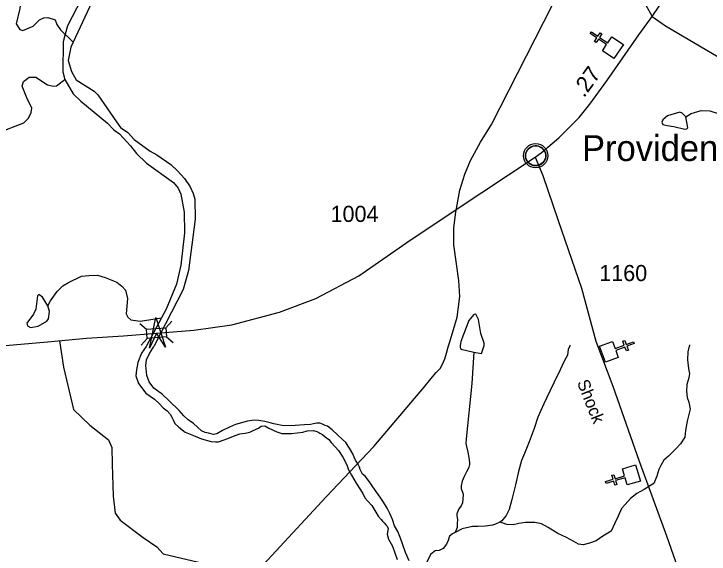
# Model space of a CAD drawing. Extents: x 2056842 to 2160602, y 826753 to 1016856.
# Drawn here: x 2095813 to 2101200, y 908514 to 912699 of the extents above; entities that cross this region are included whole.
import ezdxf

# ---------------------------------------------------------------- set-up
doc = ezdxf.new("R2010")
doc.units = 0
for name, color, linetype in [('Exist Civil Demographics Community CELL', 7, 'Continuous'), ('Exist Civil Demographics Community Label', 7, 'Continuous'), ('Exist Cultural Church CELL', 7, 'Continuous'), ('Exist Hydrographic Creek Single Shore', 7, 'Continuous'), ('Exist Hydrographic Misc Water Feature', 7, 'Continuous'), ('Exist Hydrographic River Shore', 7, 'Continuous'), ('Exist Railroad Mainline', 7, 'Continuous'), ('Exist Road Non-System Type 51', 7, 'Continuous'), ('Exist Road Secondary Mileage Hundredths English Label', 7, 'Continuous'), ('Exist Road Secondary Structure Standard Bridge Attributed CELL', 7, 'Continuous'), ('Exist Road Secondary Structure Standard Bridge CELL', 7, 'Continuous'), ('Exist Road Secondary Type 51 Attributed', 7, 'Continuous'), ('Exist Road Secondary Type 51 Label', 7, 'Continuous'), ('Exist Road Secondary Type 51 Number Label', 7, 'Continuous')]:
    doc.layers.add(name, color=color, linetype=linetype)

msp = doc.modelspace()

# ---------------------------------------------------------------- linework, layer by layer
at = {"layer": 'Exist Civil Demographics Community CELL'}
msp.add_lwpolyline([(2099778.8, 911613.1), (2099779.7, 911618.7), (2099781.5, 911625.2), (2099784.4, 911632.4), (2099787.4, 911638.2), (2099790.7, 911643.9), (2099794.5, 911649), (2099798.4, 911653.4), (2099803, 911658), (2099808.6, 911662.6), (2099814, 911666.3), (2099818.9, 911669.1), (2099823.9, 911671.6), (2099829.4, 911673.9), (2099835, 911675.7), (2099839.3, 911676.8), (2099844.2, 911677.6), (2099848.3, 911678.3), (2099854.7, 911678.6), (2099859.1, 911678.5), (2099864.8, 911678.2), (2099869.7, 911677.5), (2099874.6, 911676.5), (2099879.6, 911675.1), (2099884.8, 911673.1), (2099891.4, 911670.2), (2099897.7, 911666.7), (2099902.7, 911663.2), (2099907.9, 911659.2), (2099911.2, 911656), (2099915.3, 911651.6), (2099919.2, 911646.9), (2099922.3, 911642.4), (2099925.4, 911637.3), (2099927.9, 911632.2), (2099929.9, 911627.2), (2099931.5, 911622.2), (2099932.7, 911617.6), (2099933.8, 911611.5), (2099934.5, 911606.8), (2099934.7, 911600.8), (2099934.5, 911595), (2099934, 911589.3), (2099933, 911583.9), (2099931.4, 911577.7), (2099929.5, 911571.9), (2099927.2, 911566.8), (2099924, 911560.8), (2099920.8, 911555.5), (2099917.3, 911550.8), (2099913.1, 911546), (2099907.8, 911541.1), (2099902.8, 911537), (2099897.8, 911533.5), (2099893.4, 911531), (2099886.6, 911527.8), (2099879.5, 911525.1), (2099873.5, 911523.6), (2099866.9, 911522.3), (2099862.5, 911521.8), (2099858, 911521.6), (2099852.4, 911521.6), (2099848.2, 911522), (2099842.5, 911522.7), (2099836.6, 911524), (2099832, 911525.3), (2099826.8, 911527.2), (2099822.2, 911529.2), (2099818.3, 911531.4), (2099811.5, 911535.5), (2099805.9, 911539.8), (2099801, 911544.3), (2099796.6, 911549.1), (2099793.4, 911553.1), (2099790.4, 911557.3), (2099786.3, 911564.4), (2099784.6, 911567.9), (2099782.9, 911571.9), (2099780.3, 911580.1), (2099778.8, 911587.2), (2099778.1, 911592.3), (2099777.7, 911598.6), (2099777.7, 911603.3), (2099778.2, 911609.8)], close=True, dxfattribs=at)
for centre, radius in [((2099856.4, 911600.7), 94.3), ((2099856.1, 911600.9), 76.7)]:
    msp.add_circle(centre, radius, dxfattribs=at)
at = {"layer": 'Exist Cultural Church CELL'}
for points in [[(2100374.5, 912414.3), (2100406.1, 912461.7), (2100342.9, 912504.1), (2100325.1, 912477.5), (2100311.8, 912486.4), (2100329.6, 912512.9), (2100279.6, 912546.4), (2100288.6, 912559.7), (2100338.5, 912526.3), (2100356.3, 912552.8), (2100369.6, 912543.9), (2100351.8, 912517.4), (2100415, 912475), (2100447.2, 912522.8), (2100535.7, 912463.5), (2100462.9, 912355)], [(2100451.8, 910161.1), (2100471.4, 910107.7), (2100543, 910133.7), (2100532, 910163.7), (2100547, 910169.2), (2100558, 910139.1), (2100614.5, 910159.7), (2100620, 910144.6), (2100563.4, 910124.1), (2100574.4, 910094), (2100559.4, 910088.5), (2100548.4, 910118.6), (2100476.9, 910092.6), (2100496.4, 910038.4), (2100396.4, 910002), (2100351.8, 910124.8)], [(2100565.1, 909049.6), (2100549.1, 909104.3), (2100476, 909083.1), (2100484.9, 909052.3), (2100469.6, 909047.9), (2100460.7, 909078.6), (2100402.9, 909061.9), (2100398.4, 909077.3), (2100456.2, 909094), (2100447.3, 909124.7), (2100462.6, 909129.2), (2100471.5, 909098.5), (2100544.7, 909119.6), (2100528.7, 909175.1), (2100631, 909204.7), (2100667.3, 909079.2)]]:
    msp.add_lwpolyline(points, close=True, dxfattribs=at)
at = {"layer": 'Exist Hydrographic Creek Single Shore'}
for points in [[(2095387.7, 912862.1), (2095435.7, 912864.4), (2095519.8, 912884.7), (2095715.7, 912903.2), (2095803.7, 912859.4), (2095840, 912819.6), (2095863.9, 912785.6), (2095860, 912741.8), (2095830.7, 912623.6), (2095858.6, 912577.7), (2095882.7, 912569.7), (2095962.5, 912604.1), (2096012.4, 912652.3), (2096044.2, 912668.4), (2096076.4, 912670.3), (2096132.5, 912652.4), (2096144.5, 912616.8), (2096174.5, 912574.8), (2096272.8, 912480.5)], [(2095673.3, 911773.4), (2095889.2, 911856.1), (2095927, 911892.1), (2095946.8, 911936.2), (2095950.7, 911968.2), (2095912.6, 912050.1), (2095876.3, 912139.9), (2095888.2, 912176), (2095932.1, 912208.1), (2095984, 912210.4), (2096072.1, 912150.6), (2096116.2, 912138.7), (2096144.1, 912142.8), (2096208.1, 912191)]]:
    msp.add_lwpolyline(points, dxfattribs=at)
at = {"layer": 'Exist Hydrographic Misc Water Feature'}
msp.add_line((2096955.7, 910345.6), (2096838.2, 910121.3), dxfattribs=at)
for points in [[(2101020.4, 911902.2), (2101060.4, 911928.3), (2101138.1, 911950.6), (2101206, 911948.8), (2101270.4, 911927)], [(2100878.3, 911909.8), (2100840.4, 911879.6), (2100832.6, 911861.7), (2100840.6, 911843.6), (2100874.7, 911833.8), (2100926.5, 911828)], [(2101020.4, 911902.2), (2100992.4, 911930.2), (2100974.3, 911938.1), (2100878.3, 911909.8)], [(2100926.5, 911828), (2101012.7, 911806.2), (2101028.6, 911808.3), (2101036.6, 911816.3), (2101020.4, 911902.2)], [(2096075.4, 910436.8), (2096095.3, 910476.9), (2096149.2, 910549.1), (2096193.1, 910591.2), (2096237, 910617.2), (2096336.9, 910667.6), (2096392.8, 910673.7), (2096460.7, 910673.9), (2096520.8, 910658.1), (2096610.8, 910620.5), (2096648.9, 910590.6), (2096677, 910558.7), (2096693.2, 910494.7), (2096683.6, 910374.8), (2096695.7, 910350.8), (2096719.7, 910328.8), (2096791.9, 910319), (2096955.7, 910345.6)], [(2096075.4, 910436.8), (2096035.4, 910504.7), (2096007.3, 910526.6), (2095995.2, 910514.5), (2095983.5, 910412.5), (2095963.9, 910372.5)], [(2096079.9, 910336.8), (2096087.7, 910392.8), (2096075.4, 910436.8)], [(2095963.9, 910372.5), (2095914, 910302.3), (2095917.9, 910282.3), (2095942.1, 910270.4), (2096002, 910280.5), (2096067.8, 910318.8), (2096079.9, 910336.8)], [(2099377.4, 910369.2), (2099337.6, 910323.1), (2099276.1, 910160.9), (2099272.2, 910128.9)], [(2099456.1, 910129.5), (2099458.2, 910149.5), (2099431.9, 910223.3), (2099413.7, 910331.3), (2099393.4, 910373.2), (2099377.4, 910369.2)], [(2099272.2, 910128.9), (2099272.4, 910116.9), (2099273.8, 910104.9), (2099278.5, 910100.9), (2099375.9, 910079.2)], [(2099375.9, 910079.2), (2099435.8, 910067.4), (2099456.1, 910129.5)], [(2101047.3, 910135.4), (2101035.6, 910082.4), (2101031.9, 910020.3), (2101038.1, 909972.3), (2101044, 909936.4), (2101048.1, 909912.4), (2101042.4, 909880.4), (2101028.4, 909828.3), (2101024.5, 909776.3), (2101030.9, 909728.3), (2101042.8, 909692.3), (2101053, 909636.4), (2101043.2, 909596.4), (2101029.3, 909544.3), (2101017.6, 909470.4), (2101011.6, 909420.3), (2100979.8, 909368.2), (2100944.2, 909332.2), (2100886.1, 909273.9), (2100850.5, 909241.8), (2100826.3, 909201.8), (2100810.7, 909169.7), (2100794.7, 909117.7), (2100772.9, 909061.6), (2100746.9, 909045.5), (2100697.1, 909015.4), (2100639, 908983.2), (2100591.3, 908945), (2100549.4, 908898.9), (2100521.6, 908866.9), (2100495.5, 908808.8), (2100469.9, 908752.7), (2100440.1, 908692.6), (2100376.2, 908652.4), (2100324.3, 908616.2), (2100272.4, 908598.1), (2100224.4, 908586), (2100188.3, 908589.9), (2100152.5, 908611.7), (2100094, 908641.6), (2100028.2, 908673.3), (2099952.1, 908721.1), (2099901.9, 908748.9), (2099849.8, 908758.8), (2099777.8, 908758.5), (2099726, 908750.4), (2099681.9, 908740.3), (2099633.9, 908744.1), (2099597.8, 908756), (2099577.9, 908761.9)], [(2100124.2, 910132), (2100119.7, 910127.5), (2100108, 910099.5), (2100103.9, 910055.5), (2100078, 910009.4), (2100046.4, 909941.3), (2100000.5, 909845.1), (2099964.8, 909777), (2099919.1, 909677), (2099873.4, 909574.7), (2099845.7, 909486.7), (2099806.1, 909382.6), (2099770.4, 909294.5), (2099746.5, 909238.5), (2099722.7, 909154.4), (2099701.1, 909050.3), (2099671.4, 908936.2), (2099649.7, 908860.1), (2099627.9, 908812.2), (2099593.9, 908772), (2099577.9, 908761.9)], [(2099375.9, 910079.2), (2099360.5, 909835.2), (2099317.9, 909407), (2099316.1, 909371), (2099320.2, 909347.1), (2099330.4, 909303.2), (2099338.4, 909263.2), (2099344.6, 909223.2), (2099342.7, 909207.2), (2099338.6, 909187.2), (2099330.6, 909169.2), (2099320.8, 909151.1), (2099302.9, 909115), (2099286.9, 909079), (2099279.1, 909042.9), (2099279.1, 909023), (2099293.3, 908979.1), (2099291.4, 908939.1), (2099289.6, 908911.1), (2099279.6, 908889.1), (2099261.7, 908865), (2099245.9, 908826.9), (2099244, 908810.8), (2099249.3, 908783), (2099248.3, 908751), (2099247.2, 908720), (2099233.3, 908681.6)], [(2099577.9, 908761.9), (2099545.9, 908745.8), (2099522.1, 908737.8), (2099468.1, 908731.7), (2099407.3, 908728.5), (2099367.8, 908727.5), (2099287.8, 908710.4), (2099233.3, 908681.6)], [(2099233.3, 908681.6), (2099210.9, 908670.9), (2099188.5, 908652.7), (2099183.2, 908637.8), (2099177.8, 908620.7), (2099166.1, 908590.8), (2099140.5, 908556.6), (2099109.5, 908542.8), (2099077.5, 908540.6), (2099043.4, 908513.9), (2098995.4, 908416.8), (2098970.8, 908357.8), (2098950.6, 908230.8)]]:
    msp.add_lwpolyline(points, dxfattribs=at)
at = {"layer": 'Exist Hydrographic River Shore'}
for points in [[(2097023, 913811.4), (2096990.8, 913793.3), (2096746.1, 913424.6), (2096545, 913152), (2096501.3, 913073.9), (2096373.8, 912889.5), (2096228.8, 912607.1), (2096210.9, 912543)], [(2096489.3, 912947.6), (2096255.1, 912440.9), (2096233.3, 912339), (2096259.7, 912253.1), (2096295.8, 912189), (2096436, 912099.5), (2096464.3, 912071.7), (2096606.9, 911862), (2096638.8, 911818.4), (2096695.2, 911780.5), (2096745.2, 911726.6), (2096869.7, 911635.1), (2096921.6, 911607.1), (2097029.9, 911531.4), (2097080.1, 911483.7), (2097134, 911423.9), (2097178.3, 911360), (2097202.5, 911307.9), (2097214.7, 911264.1), (2097217, 911108.1), (2097166.5, 910712.2), (2097124.7, 910564.1), (2096898, 910121.5)], [(2096210.9, 912543), (2096195.2, 912483), (2096191.9, 912251), (2096208.1, 912191)], [(2096208.1, 912191), (2096272.5, 912081.2), (2096330.5, 912023.4), (2096539, 911852.1), (2096587.2, 911802.3), (2096631.3, 911770.4), (2096717.6, 911676.6), (2096761.7, 911616.9), (2096840, 911543.1), (2097050.4, 911393.8), (2097086.7, 911349.9), (2097106.8, 911302), (2097133.1, 911164), (2097133.7, 911004.1), (2097106.4, 910752), (2097072.8, 910606), (2096991.6, 910411.7), (2096955.7, 910345.6)], [(2096838.2, 910121.3), (2096802.5, 910070.1), (2096772.6, 909998.6), (2096764.1, 909942), (2096758.7, 909895), (2096778, 909835.2), (2096834.5, 909761.5), (2096901.2, 909715.6), (2096939.3, 909679.7), (2096969.4, 909647.8), (2097001.6, 909623.9), (2097023.6, 909597.9), (2097037.7, 909574), (2097047.8, 909554), (2097059.9, 909526), (2097090, 909498.2), (2097140, 909458.4), (2097204.2, 909432.5), (2097266.1, 909406.8), (2097342.4, 909386.9), (2097374.4, 909383.1), (2097398.4, 909383.1), (2097470.2, 909409.4), (2097528.2, 909433.6), (2097564.1, 909445.7), (2097604.1, 909449.8), (2097640.2, 909459.9), (2097666.8, 909471.2), (2097707.4, 909490.5), (2097729.8, 909504.3), (2097756.5, 909507.5), (2097788.5, 909490.5), (2097851.4, 909460.6), (2097888.1, 909448.6), (2097932.2, 909448.7), (2097964.1, 909448.9), (2098052.1, 909458.4), (2098086.2, 909469.1), (2098135.8, 909471.4), (2098160, 909463.5), (2098176, 909455.5), (2098184, 909451.6), (2098204.1, 909439.6), (2098224.1, 909423.7), (2098254.1, 909401.8), (2098272.1, 909377.9), (2098302.3, 909346), (2098328.3, 909318), (2098362.6, 909266.1), (2098393.5, 909204.8), (2098405.3, 909166.4), (2098428.7, 909126.9), (2098466.1, 909064.1), (2098516.2, 908983), (2098532.3, 908948.8), (2098553.6, 908927.5), (2098587.7, 908891.2), (2098617.6, 908838.8), (2098634.7, 908807.9), (2098658.2, 908781.2), (2098670.1, 908769.2), (2098682, 908757.2), (2098694.1, 908741.2), (2098706, 908729.3), (2098712.2, 908713.3), (2098706.2, 908669.6), (2098716.9, 908629), (2098745.7, 908575.6), (2098782, 908471)], [(2098876.9, 908461.6), (2098847, 908526.5), (2098823.6, 908592.7), (2098808.6, 908638.6), (2098788.1, 908689.5), (2098761.7, 908733.7), (2098746.7, 908781.7), (2098725.7, 908829.3), (2098705.5, 908869.1), (2098677.3, 908916.9), (2098651.2, 908954.8), (2098625, 908990.8), (2098595.1, 909034.8), (2098572.8, 909066.7), (2098536.5, 909115.2), (2098514.8, 909134.5), (2098505.6, 909148.3), (2098496, 909170.7), (2098490.6, 909188.8), (2098475.7, 909217.7), (2098460.3, 909242.3), (2098450.2, 909264.2), (2098438.3, 909290.3), (2098414.3, 909334.1), (2098384, 909378.1), (2098360.5, 909401.8), (2098321, 909439.2), (2098279.4, 909476.6), (2098243.6, 909505.7), (2098223.7, 909511.7), (2098203.5, 909519.6), (2098183.7, 909527.3), (2098159.7, 909527.4), (2098135.7, 909523.3), (2098111.7, 909519.2), (2098065.9, 909515), (2098028.6, 909513.9), (2097991.2, 909509.7), (2097907.7, 909508.7), (2097875.6, 909512.3), (2097851.8, 909518.4), (2097827.6, 909524.5), (2097799.6, 909532.3), (2097758.6, 909541.7), (2097710.6, 909550.2), (2097674.3, 909551.3), (2097623.1, 909544.9), (2097576.1, 909532.1), (2097531.3, 909517.1), (2097483.3, 909497.9), (2097428.9, 909472.3), (2097385.1, 909445.6), (2097358.5, 909441.3), (2097320, 909449.9), (2097295.5, 909456.3), (2097267.8, 909470.2), (2097203.6, 909526.2), (2097163.5, 909554.3), (2097129.4, 909586.2), (2097093.4, 909626), (2097017.3, 909701.7), (2096963.2, 909751.7), (2096897.5, 909800), (2096862.3, 909849.1), (2096844.1, 909898.2), (2096835.6, 909976.2), (2096840.9, 910018.9), (2096864.4, 910069), (2096889.9, 910109.2), (2096898, 910121.5)]]:
    msp.add_lwpolyline(points, dxfattribs=at)
at = {"layer": 'Exist Railroad Mainline'}
msp.add_lwpolyline([(2097583.5, 908256.7), (2098233.2, 908956.5), (2098602, 909347.7), (2098988.6, 909804.8), (2099044.2, 909873), (2099084.2, 909921.2), (2099116.1, 909951.2), (2099132.1, 909981.2), (2099151.8, 910027.2), (2099166, 910071.2), (2099176.2, 910108.5), (2099179.9, 910128.2), (2099192.1, 910159.9), (2099247.1, 910350.4), (2099268.6, 910510.4), (2099260.2, 910634.4), (2099223.3, 910910.2), (2099223.1, 911042.2), (2099236.6, 911162.3), (2099268.1, 911334.3), (2099307.7, 911458.5), (2099351.3, 911562.6), (2099428.8, 911704.8), (2099514.5, 911843.1), (2099985.4, 912770.4)], dxfattribs=at)
at = {"layer": 'Exist Road Non-System Type 51'}
msp.add_lwpolyline([(2096166, 910166.9), (2096196.6, 909962.2), (2096275.6, 909635.1), (2096402.2, 909513.7), (2096546, 909398.7), (2096572.9, 909339.4), (2096574.7, 909211.8), (2096581, 908962.8), (2096598.9, 908831.6), (2096636.7, 908777.6), (2096814.5, 908642.8), (2096920.5, 908570.9), (2096969, 908517), (2097242.9, 908451.4), (2097386.6, 908413.6), (2097501.6, 908298.6), (2097582.4, 908201.5)], dxfattribs=at)
at = {"layer": 'Exist Road Secondary Structure Standard Bridge Attributed CELL'}
msp.add_lwpolyline([(2096862.7, 910108.5), (2096911.5, 910347.4), (2096988.7, 910116.1), (2096918.9, 910225.7)], close=True, dxfattribs=at)
at = {"layer": 'Exist Road Secondary Structure Standard Bridge CELL'}
for p, q in [((2096787.7, 910301), (2096840, 910256)), ((2096990.7, 910266.9), (2097035.7, 910319.2)), ((2096800.2, 910133.3), (2096845.2, 910185.6)), ((2096995.8, 910198.1), (2097048.1, 910153.1))]:
    msp.add_line(p, q, dxfattribs=at)
msp.add_lwpolyline([(2096840, 910256), (2096990.7, 910267.2), (2096995.9, 910196.8), (2096845.2, 910185.6)], close=True, dxfattribs=at)
at = {"layer": 'Exist Road Secondary Type 51 Attributed'}
for points in [[(2098614.9, 916854.6), (2098755.8, 916709), (2098879.7, 916576), (2098948, 916475.4), (2099042.2, 916223), (2099150, 915890.5), (2099269.4, 915553.6), (2099362.8, 915246.3), (2099438.2, 915108), (2099708.4, 914607.5), (2099857.5, 914327.2), (2100185.2, 913711.8), (2100340.8, 913433.7), (2100759.3, 912678.1)], [(2100759.3, 912678.1), (2100920.9, 912920.7), (2101237, 913373.5), (2101874.4, 914273.8), (2102208.4, 914762.5), (2102659.1, 915413)], [(2099852.1, 911588.7), (2099899.7, 911623.8), (2100035.7, 911740.1), (2100193.7, 911896.4), (2100276.3, 912000.7), (2100406.5, 912180.4), (2100655.6, 912537.5), (2100759.3, 912678.1)], [(2100759.3, 912678.1), (2100862.1, 912607.6), (2101314.6, 912341.6), (2101818.3, 912042.4), (2102193.6, 911816), (2102497.1, 911638.1), (2102675.7, 911549.2), (2102765.5, 911516.9), (2102889.4, 911502.5), (2103194.7, 911504.3), (2103415.6, 911509.7), (2103526, 911480), (2103657.1, 911409.9), (2103752.2, 911307.5), (2103904.9, 911099.1), (2104095, 910825.1)], [(2096918.9, 910225.7), (2097207, 910249), (2097501.6, 910290.3), (2097871.6, 910389.2), (2098151.9, 910493.4), (2098486.9, 910670.5), (2098858.7, 910927.5), (2099232.5, 911177.6), (2099852.1, 911588.7)], [(2099852.1, 911588.7), (2099911.7, 911448.2), (2100030.3, 911099.4), (2100210.8, 910573.6), (2100321.3, 910162.8), (2100454.3, 909815.9), (2100658.2, 909234.3), (2100869.2, 908654.6), (2100991.4, 908309.4), (2101164.7, 907792.6), (2101361.4, 907238), (2101435.1, 907083.4), (2101537.5, 906912.6), (2101734.2, 906658.2), (2102071.9, 906295.1), (2102423.1, 905907.7), (2102599.2, 905769.3), (2102771.6, 905666.8), (2103021.3, 905555.3), (2103859.4, 905243.4), (2104202.5, 905126.6)], [(2092880.7, 909721.2), (2093053.9, 909781.6), (2093359.3, 909867.9), (2093737.4, 909940.7), (2094191.9, 909994.6), (2095241.8, 910087.2), (2096074.4, 910158.2), (2096376.2, 910186.9), (2096661.8, 910204.9), (2096918.9, 910225.7)]]:
    msp.add_lwpolyline(points, dxfattribs=at)

# ---------------------------------------------------------------- texts
at = {"layer": 'Exist Civil Demographics Community Label'}
msp.add_text('Providence', height=200, dxfattribs=at).set_placement((2100215.4, 911559.7))
at = {"layer": 'Exist Road Secondary Mileage Hundredths English Label'}
msp.add_text('.27', height=125, rotation=54.0768, dxfattribs=at).set_placement((2100231.1, 912044.8))
at = {"layer": 'Exist Road Secondary Type 51 Label'}
msp.add_text('Shock', height=95, rotation=291.7179, dxfattribs=at).set_placement((2100174.9, 909844.4))
at = {"layer": 'Exist Road Secondary Type 51 Number Label'}
for s, p in [('1004', (2098266.5, 911087.3)), ('1160', (2100348.5, 910629))]:
    msp.add_text(s, height=125, dxfattribs=at).set_placement(p)

doc.saveas('drawing.dxf')
